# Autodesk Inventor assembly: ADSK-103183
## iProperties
Shininess: 0.0
Created: 2000-07
Part Number: ADSK-103183
Document SubType Name: Assembly
Stock Number: ADSK-103183
Density: 0.0
Volumn: 0.0
Area: 0.0
PropertySet Name: Model Information
Control State: 0
Master: False
Checked Out: False
Author: gao
